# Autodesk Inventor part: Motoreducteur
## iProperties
Shininess: 64.0
Length Units: 11269
Angle Units: 11279
Time Units: 11290
Mass Units: 11283
Length Display Precision: 3
Angle Display Precision: 2
Compacted: True
Part Number: Motoreducteur
Document SubType Name: Modeling
Created: 2008-03
Material: Titane
Designer: Pascal
Density: 0.0
Volumn: 0.0
Area: 0.0
PropertySet Name: Model Information
Control State: 0
Master: False
Checked Out: False
OBSERVATIONS: Masse 137 Kg
DESIGNATION: Motoréducteur F50 2H50
Author: Pascal
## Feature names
1. Extrusion1
2. Extrusion2
3. Symétrie1 [Mirror]
4. Chanfrein1 [Chamfer]
5. Extrusion3
6. Extrusion4
7. Extrusion5
8. Extrusion8
9. Extrusion9
10. Extrusion10
11. Chanfrein2 [Chamfer]
12. Extrusion11
13. Extrusion12
14. Extrusion13
15. Extrusion14
16. Chanfrein3 [Chamfer]
17. Extrusion15
18. Congé2 [Fillet]
19. Extrusion16
20. Réseau circulaire1 [Circular Pattern]
21. Extrusion17
22. Extrusion18
23. Extrusion19
24. Extrusion20
25. Extrusion21
26. Extrusion22
